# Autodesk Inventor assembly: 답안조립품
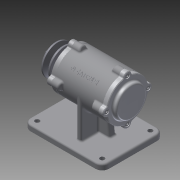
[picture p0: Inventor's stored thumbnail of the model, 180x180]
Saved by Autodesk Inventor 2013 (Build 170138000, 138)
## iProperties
Created: 2015-12
Part Number: 답안조립품
Document SubType Name: Assembly
Designer: a
Author: a
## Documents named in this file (11)
- C:\Documents and Settings\a\바탕 화면\451208V1004\답안조립품.iam
- C:\Documents and Settings\a\바탕 화면\451208V1004\본체.ipt
- C:\Documents and Settings\a\바탕 화면\451208V1004\커버.ipt
- C:\Documents and Settings\a\바탕 화면\451208V1004\베어링 6204.ipt
- C:\Documents and Settings\a\바탕 화면\451208V1004\커버2.ipt
- C:\Documents and Settings\a\바탕 화면\451208V1004\오일실.ipt
- C:\Documents and Settings\a\바탕 화면\451208V1004\축.ipt
- C:\Documents and Settings\a\바탕 화면\451208V1004\키(4 x 4 x 12).ipt
- C:\Documents and Settings\a\바탕 화면\451208V1004\V-벨트풀리.ipt
- C:\Documents and Settings\a\바탕 화면\451208V1004\너트 M12x1.25.ipt
- C:\Documents and Settings\a\바탕 화면\451208V1004\볼트 M4 x 12.ipt
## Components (6 placed, 5 different names)
1. KS B 2023 6204 - 20 x 47 x 14:1
2. KS B 2023 6204 - 20 x 47 x 14:2
3. KS B 2804 D D - 20 32 8:1
4. KS B 1311 (I) 4 x 4 x 12:1
5. V-벨트풀리:1
6. KS B 1012 클래스 1 일반 - 미터 M12x1.25:1 — 각도:1
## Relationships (1: Angle 1)
- 각도:1 [Angle]: KS B 1012 클래스 1 일반 - 미터 M12x1.25:1
